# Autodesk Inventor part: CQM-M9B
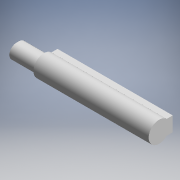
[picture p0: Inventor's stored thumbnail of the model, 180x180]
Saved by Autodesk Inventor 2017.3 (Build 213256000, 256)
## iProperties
Part Number: CQM-M9B
Material: Generic
Catalog Web Link: www.cadenas.de
Description: CQM_SW-Compact Cylinder Guide Rod Type
Vendor: SMC
Document SubType Name: Modeling
Designer: partserver
Manufacturer: SMC
Mass: 0.35879 g
Surface Area: 3.99853 cm^2
Volume: 0.35879 cm^3
Density: 1 g/cm^3
Appearance: PSOLRGB-255-255-255
Category: PARTsolutions
Company: SMC
Title: CQM-M9B
Author: Cadenas PARTsolutions
Comments: Compact Cylinder Guide Rod Type
PSOL_IDENT_0: {$CADENAS_DATA\23d-libs\smc_jp\actuator\compact_cylinder\cqm\parts\cqm_sw.prj},165 {VTYP=3D},{NB=CQM
PSOL_IDENT_1: -M9B},{LINA=CQM-M9B},{NN=CQM_SW},{DATE=09.12.2020 02:52:29},{GEOMDATE=22.11.2010 00:00:00},{VERSION=
PSOL_IDENT_2: },{LINEID=360},{WBVAR=AUTOSWITCH},{WBNUMERIC=}  {NB=CQM-M9B},{LINA=CQM-M9B},{KT=DUMMY},{AUTOSWITCH=-
PSOL_IDENT_3: M9B},{ASL=22},{SWITCHNO=6},{SWITCHS=}
NB: CQM-M9B
NN: CQM_SW
NT: Compact Cylinder Guide Rod Type
NBSYN: CQM$AUTOSWITCH.
LINA: CQM-M9B
CATALOG: SMC (JP
AUTOSWITCH: M9B
SUPPLIER: SMC
ARTICLENO: CQM-M9B
BOMINFO: CQM-M9B
CREATOR: CADENAS GmbH
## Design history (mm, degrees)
sketch "Sketch_1"
  geometry: L1 (1.428, -1.4)-(2.6, -1.4); L2 (2.6, -1.4)-(2.6, 1.4); L3 (2.6, 1.4)-(1.428, 1.4); A1 r 2 centre (0, 0) between (1.428, 1.4) and (1.428, -1.4)
  constraints: 6 end point, 2 point on circle, 1 centre point
extrude "Extrusion1" join sketch "Sketch_1" distance "d0" = 22; taper "d1" = 0 deg
sketch "Sketch_2"
  geometry: L1 (0.25, 1.35)-(-0.25, 1.35); L2 (-0.25, -1.35)-(0.25, -1.35); A1 r 1.35 centre (-0.25, 0) between (-0.25, 1.35) and (-0.25, -1.35); A2 r 1.35 centre (0.25, 0) between (0.25, -1.35) and (0.25, 1.35)
  constraints: 4 end point, 4 point on circle, 2 centre point
extrude "Extrusion2" join sketch "Sketch_2" distance "d2" = 27; taper "d3" = 0 deg
sketch "Sketch3"
  geometry: 1 further point
hole "Hole1" sketch "Sketch3" at (2, 1.4) diameter "d4" = 2.5; stored, may be unused: countersink angle "d8" = 90 deg, drill point angle "d10" = 0 deg; dims "d5" = 6, "d6" = 4, "d7" = 2, "d9" = 0.2
node "SW_SM_XY"
node "SW_SM_YZ"
node "SW_SM_ZX"
node "SW_SM_X"
node "SW_SM_Y"
node "SW_SM_Z"
node "SW_SM_Center"
body "Solid1"
other parameters: "d11" = 0
